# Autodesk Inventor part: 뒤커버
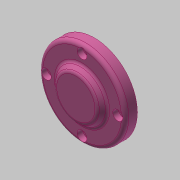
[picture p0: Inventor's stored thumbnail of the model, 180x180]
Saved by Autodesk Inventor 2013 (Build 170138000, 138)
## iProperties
Created: 2017-08
Part Number: 뒤커버
Material: 알루미늄 6061
Document SubType Name: Modeling
Designer: mduedu
Density: 2.71 g/cm^3
Mass: 99.1174 g
Surface Area: 135.95 cm^2
Volume: 36.5747 cm^3
Author: mduedu
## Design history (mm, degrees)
sketch "스케치1"
  geometry: C1 r 35 at (0, 0); 1 further point
  constraints: 1 centre point, 1 coincident
  dimensions: "d0" = 70 diameter of C1
extrude "돌출1" new body sketch "스케치1" distance "d1" = 10; taper "d2" = 0 deg
sketch "스케치2"
  geometry: C1 r 21 at (0, 0); 1 further point
  constraints: 1 centre point, 1 coincident
  dimensions: "d3" = 42 diameter of C1
node "작업 평면1"
sketch "스케치3"
  geometry: C1 r 17 at (0, 0); 1 further point
  constraints: 1 centre point, 1 coincident
  dimensions: "d5" = 34 diameter of C1
feature "로프트1" sketch "스케치3" dims "d6" = 0, "d7" = 90 deg, "d8" = 0, "d9" = 90 deg
sketch "스케치4"
  geometry: C1 r 24 at (0, 0); 1 further point
  constraints: 1 centre point, 1 coincident
  dimensions: "d65" = 48 diameter of C1
extrude "돌출2" join sketch "스케치4" distance "d10" = 8; taper "d11" = 0 deg
hole "구멍1" diameter "d14" = 40; stored, may be unused: countersink angle "d18" = 90 deg, drill point angle "d20" = 0 deg; dims "d15" = 6, "d16" = 4, "d17" = 2, "d19" = 12, "d66" = 10, "d67" = 10
hole "구멍2" diameter "d23" = 34; stored, may be unused: countersink angle "d27" = 90 deg, drill point angle "d29" = 0 deg; dims "d24" = 6, "d25" = 4, "d26" = 2, "d28" = 6, "d62" = 10, "d63" = 10
chamfer "모따기1" distance "d39" = 1; stored, may be unused: second distance "d40" = 2, angle "d41" = 45 deg
fillet "모깎기1" dims "d42" = 0.3
fillet "모깎기2" dims "d43" = 3
sketch "스케치5" dims "d44" = 58
  geometry: 6 further points
  constraints: 2 vertical alignment, 1 coincident, 7 other
  dimensions: "d47" = 360 deg dimension on point (0, 0) point (0, 29) (derived)
sketch "스케치6" dims "d64" = 58 (derived)
  geometry: 6 further points
  constraints: 1 coincident, 1 vertical alignment, 6 other
hole "구멍4" sketch "스케치6" at (0, 29), (-29, 0), (29, 0), (0, -29) diameter "d49" = 4.5; stored, may be unused: countersink angle "d53" = 90 deg, drill point angle "d55" = 0 deg; dims "d50" = 6, "d51" = 8, "d52" = 4.6, "d54" = 8
fillet "모깎기3" dims "d56" = 3
fillet "모깎기4" dims "d57" = 3
fillet "모깎기5" dims "d58" = 3
node "솔리드1"
other parameters: "d4" = 5
